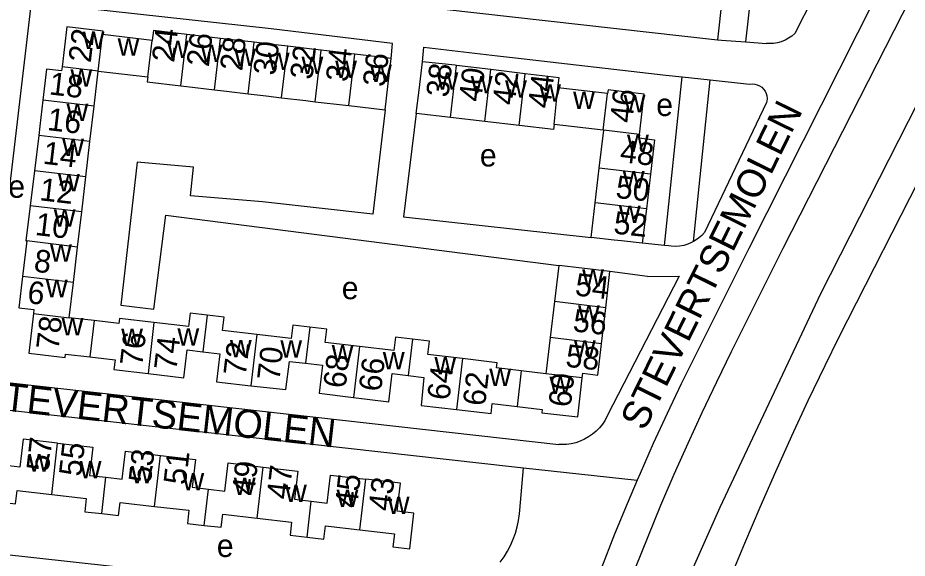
# Model space of a CAD drawing. Extents: x 159902 to 161769, y 383692 to 384875.
# Drawn here: x 161393 to 161550.6, y 384324.5 to 384420.2 of the extents above; entities that cross this region are included whole.
import ezdxf

# ---------------------------------------------------------------- set-up
doc = ezdxf.new("R2010")
doc.units = 0
for name, color, linetype in [('BLT_Basislijn', 7, 'Continuous'), ('BLT_Bebouwing', 7, 'Continuous'), ('BLT_Centroide', 7, 'Continuous'), ('BLT_Huisnummer', 7, 'Continuous'), ('BLT_Huisnummer_ tussenligend', 7, 'Continuous'), ('BLT_Onderverdeling_panden', 7, 'Continuous'), ('BLT_Straatnaam', 7, 'Continuous')]:
    doc.layers.add(name, color=color, linetype=linetype)

msp = doc.modelspace()

# ---------------------------------------------------------------- linework, layer by layer
at = {"layer": 'BLT_Basislijn'}
for p, q in [((161566.13, 384465.78), (161522.6, 384379.3)), ((161572.32, 384465.07), (161528.61, 384379.3)), ((161582.61, 384464.51), (161535.3, 384371.31)), ((161538.52, 384363.54), (161589.05, 384462.81)), ((161520.47, 384447.58), (161517, 384416.3)), ((161525.45, 384447.03), (161521.99, 384415.92)), ((161544.71, 384444.9), (161530.71, 384417.4)), ((161517, 384416.3), (161517.76, 384416.22)), ((161517.76, 384416.22), (161521.99, 384415.92)), ((161521.99, 384415.92), (161525.72, 384415.65)), ((161507.66, 384379.85), (161510.74, 384409.69)), ((161507.85, 384410), (161510.74, 384409.69)), ((161510.74, 384409.69), (161515.71, 384409.16)), ((161512.75, 384380.53), (161515.71, 384409.16)), ((161515.71, 384409.16), (161522.72, 384408.4)), ((161525.72, 384405.15), (161514.73, 384382.16)), ((161507.66, 384379.85), (161503.7, 384380.25)), ((161508.41, 384379.77), (161507.66, 384379.85)), ((161522.6, 384379.3), (161515.81, 384365.72)), ((161528.61, 384379.3), (161519.47, 384361.02)), ((161504.59, 384374.34), (161497.94, 384375.22)), ((161535.3, 384371.31), (161517.42, 384333.41)), ((161481.08, 384340.63), (161482.62, 384340.46)), ((161481.98, 384332.97), (161482.62, 384340.46)), ((161482.62, 384340.46), (161502.77, 384338.26)), ((161463.15, 384317.18), (161383.46, 384325.86))]:
    msp.add_line(p, q, dxfattribs=at)
for points in [[(161509.61, 384484.47), (161452.16, 384490.71), (161444.37, 384424.47), (161517, 384416.3)], [(161459.19, 384412.99), (161459.41, 384415.65), (161437.91, 384418.21), (161395.42, 384422.86), (161387.74, 384357.97), (161387.49, 384355.98), (161488.9, 384344.6)], [(161530.71, 384417.4), (161530.19, 384416.94), (161529.61, 384416.54), (161528.99, 384416.2), (161528.33, 384415.94), (161527.65, 384415.76), (161526.96, 384415.65), (161526.26, 384415.62), (161525.72, 384415.65)], [(161464.72, 384412.35), (161464.96, 384414.95), (161478.04, 384413.44), (161481.21, 384413.08), (161507.85, 384410)], [(161522.72, 384408.4), (161523.17, 384408.45), (161523.63, 384408.42), (161524.07, 384408.31), (161524.48, 384408.12), (161524.86, 384407.87), (161525.19, 384407.55), (161525.45, 384407.18), (161525.65, 384406.77), (161525.77, 384406.33), (161525.82, 384405.88), (161525.78, 384405.43), (161525.72, 384405.15)], [(161458.12, 384403.87), (161455.96, 384385.38), (161436.42, 384387.6), (161423.61, 384388.66), (161424.15, 384393.7), (161414.18, 384394.6), (161411.29, 384369.3), (161417.16, 384368.59), (161419.26, 384385.22), (161488.88, 384376.28)], [(161463.65, 384403.23), (161461.39, 384384.91), (161494.65, 384381.24)], [(161514.73, 384382.16), (161514.23, 384381.61), (161513.67, 384381.13), (161513.07, 384380.71), (161512.75, 384380.53)], [(161512.75, 384380.53), (161512.43, 384380.35), (161511.74, 384380.07), (161511.04, 384379.86), (161510.31, 384379.73), (161509.58, 384379.68), (161508.84, 384379.72), (161508.41, 384379.77)], [(161504.59, 384374.34), (161510.23, 384374.41), (161497.49, 384349.66)], [(161515.81, 384365.72), (161513.16, 384360.54), (161510.59, 384355.32), (161508.08, 384350.07), (161505.65, 384344.78), (161503.29, 384339.46), (161502.77, 384338.26)], [(161505.05, 384281.8), (161507.22, 384288.35), (161509.47, 384294.89), (161511.8, 384301.39), (161514.2, 384307.87), (161516.68, 384314.32), (161519.23, 384320.74), (161521.86, 384327.13), (161524.56, 384333.49), (161527.33, 384339.82), (161530.18, 384346.11), (161533.1, 384352.38), (161536.09, 384358.6), (161538.52, 384363.54)], [(161519.47, 384361.02), (161516.82, 384355.64), (161514.24, 384350.22), (161511.74, 384344.78), (161509.31, 384339.29), (161506.95, 384333.78), (161504.66, 384328.24), (161502.45, 384322.66), (161500.32, 384317.06), (161498.26, 384311.43), (161496.27, 384305.77), (161494.36, 384300.09), (161492.53, 384294.38), (161490.77, 384288.65), (161490.23, 384286.84)], [(161383.46, 384325.86), (161386.25, 384351.26), (161481.08, 384340.63)], [(161497.49, 384349.66), (161497.09, 384348.92), (161496.63, 384348.22), (161496.11, 384347.56), (161495.52, 384346.96), (161494.88, 384346.41), (161494.19, 384345.93), (161493.46, 384345.52), (161492.69, 384345.18), (161491.9, 384344.91), (161491.08, 384344.72), (161490.25, 384344.61), (161489.41, 384344.58), (161488.9, 384344.6)], [(161502.77, 384338.26), (161501, 384334.11), (161498.78, 384328.73), (161496.32, 384322.46)], [(161517.42, 384333.41), (161505.94, 384307.49)], [(161478.53, 384323.76), (161479.21, 384324.71), (161479.82, 384325.7), (161480.35, 384326.73), (161480.82, 384327.8), (161481.21, 384328.9), (161481.53, 384330.02), (161481.77, 384331.16), (161481.93, 384332.32), (161481.98, 384332.97)]]:
    msp.add_lwpolyline(points, dxfattribs=at)
at = {"layer": 'BLT_Bebouwing'}
for p, q in [((161416.82, 384416.18), (161408.04, 384417.19)), ((161424.06, 384417.11), (161422.99, 384417.23)), ((161428.95, 384416.53), (161424.06, 384417.11)), ((161431.08, 384416.28), (161428.95, 384416.53)), ((161434.9, 384415.84), (161431.08, 384416.28)), ((161438.11, 384415.46), (161434.9, 384415.84)), ((161440.86, 384415.14), (161438.11, 384415.46)), ((161445.14, 384414.63), (161440.86, 384415.14)), ((161446.82, 384414.44), (161445.14, 384414.63)), ((161452.16, 384413.81), (161446.82, 384414.44)), ((161452.78, 384413.74), (161452.16, 384413.81)), ((161459.19, 384412.99), (161452.78, 384413.74)), ((161406.55, 384404.51), (161407.29, 384410.75)), ((161407.29, 384410.75), (161416.07, 384409.72)), ((161476.87, 384411.01), (161470.8, 384411.75)), ((161482.94, 384410.26), (161476.87, 384411.01)), ((161421.92, 384408.12), (161422.99, 384407.99)), ((161422.99, 384407.99), (161427.88, 384407.42)), ((161427.88, 384407.42), (161430.01, 384407.17)), ((161430.01, 384407.17), (161433.84, 384406.72)), ((161497.51, 384406.79), (161488.75, 384407.79)), ((161433.84, 384406.72), (161437.04, 384406.34)), ((161437.04, 384406.34), (161439.79, 384406.02)), ((161439.79, 384406.02), (161444.07, 384405.52)), ((161405.82, 384398.27), (161406.55, 384404.51)), ((161444.07, 384405.52), (161445.75, 384405.32)), ((161445.75, 384405.32), (161451.09, 384404.69)), ((161451.09, 384404.69), (161451.71, 384404.62)), ((161451.71, 384404.62), (161458.12, 384403.87)), ((161469.73, 384402.52), (161463.65, 384403.23)), ((161475.8, 384401.82), (161469.73, 384402.52)), ((161481.88, 384401.11), (161475.8, 384401.82)), ((161496.76, 384400.28), (161488.06, 384401.3)), ((161396.76, 384399.33), (161395.99, 384393.09)), ((161496.08, 384393.52), (161496.87, 384400.27)), ((161496.87, 384400.27), (161496.76, 384400.28)), ((161405.09, 384392.02), (161405.82, 384398.27)), ((161395.99, 384393.09), (161395.23, 384386.85)), ((161495.37, 384387.41), (161496.08, 384393.52)), ((161404.36, 384385.78), (161405.09, 384392.02)), ((161505.13, 384392.46), (161504.42, 384386.35)), ((161494.65, 384381.24), (161495.37, 384387.41)), ((161403.62, 384379.54), (161404.36, 384385.78)), ((161504.42, 384386.35), (161503.7, 384380.25)), ((161394.62, 384380.67), (161393.86, 384374.35)), ((161402.89, 384373.29), (161403.62, 384379.54)), ((161488.88, 384376.28), (161488.13, 384369.9)), ((161497.21, 384368.83), (161497.94, 384375.22)), ((161402.16, 384367.05), (161402.89, 384373.29)), ((161488.13, 384369.9), (161487.38, 384363.52)), ((161496.47, 384362.45), (161497.21, 384368.83)), ((161406.55, 384366.54), (161402.16, 384367.05)), ((161487.38, 384363.52), (161486.63, 384357.14)), ((161486.63, 384357.14), (161482.24, 384357.65))]:
    msp.add_line(p, q, dxfattribs=at)
for points in [[(161408.04, 384417.19), (161408.14, 384417.79), (161401.71, 384418.55), (161400.89, 384411.5)], [(161422.99, 384417.23), (161417.06, 384417.93), (161416.82, 384416.18)], [(161458.12, 384403.87), (161458.61, 384408.02), (161459.19, 384412.99)], [(161463.65, 384403.23), (161464.14, 384407.38), (161464.72, 384412.35)], [(161470.8, 384411.75), (161470.54, 384411.78), (161464.72, 384412.35)], [(161400.89, 384411.5), (161400.8, 384410.78), (161398.11, 384411.1), (161397.48, 384405.57)], [(161416.07, 384409.72), (161415.96, 384408.82), (161421.92, 384408.12)], [(161488.75, 384407.79), (161488.97, 384409.53), (161482.94, 384410.26)], [(161503.22, 384399.53), (161504.02, 384406.63), (161500, 384407.11), (161497.62, 384407.39), (161497.51, 384406.79)], [(161397.48, 384405.57), (161396.96, 384400.99), (161396.76, 384399.33)], [(161488.06, 384401.3), (161487.95, 384400.4), (161481.88, 384401.11)], [(161503.22, 384399.53), (161503.15, 384398.9), (161505.84, 384398.56), (161505.13, 384392.46)], [(161395.23, 384386.85), (161394.48, 384380.67), (161394.62, 384380.67)], [(161503.7, 384380.25), (161500, 384380.66), (161498.73, 384380.8), (161494.65, 384381.24)], [(161497.94, 384375.22), (161492.98, 384375.8), (161488.88, 384376.28)], [(161393.86, 384374.35), (161393.2, 384368.83), (161395.89, 384368.51), (161395.8, 384367.78)], [(161395.8, 384367.78), (161394.99, 384360.76), (161401.42, 384360), (161401.48, 384360.59), (161405.79, 384360.11)], [(161426.59, 384367.48), (161423.58, 384367.83), (161423.3, 384365.5), (161417.17, 384366.22)], [(161417.17, 384366.22), (161411.05, 384366.93), (161410.94, 384366.02), (161406.55, 384366.54)], [(161435.41, 384364.09), (161429.32, 384364.8), (161429.6, 384367.12), (161426.59, 384367.48)], [(161444.78, 384365.35), (161441.77, 384365.71), (161441.5, 384363.37), (161435.41, 384364.09)], [(161453.59, 384361.95), (161447.52, 384362.66), (161447.79, 384365), (161444.78, 384365.35)], [(161462.95, 384363.26), (161459.95, 384363.62), (161459.67, 384361.23), (161453.59, 384361.95)], [(161471.82, 384359.8), (161465.68, 384360.52), (161465.96, 384362.91), (161462.95, 384363.26)], [(161493.05, 384356.39), (161493.14, 384357.21), (161495.83, 384356.9), (161496.47, 384362.45)], [(161405.79, 384360.11), (161410.28, 384359.61), (161410.08, 384357.9), (161416.11, 384357.17)], [(161416.11, 384357.17), (161422.43, 384356.41), (161423.05, 384361.38), (161425.83, 384361.03)], [(161425.83, 384361.03), (161428.86, 384360.66), (161428.24, 384355.68), (161434.35, 384355.01)], [(161434.35, 384355.01), (161440.56, 384354.32), (161441.19, 384359.32), (161444.04, 384358.99)], [(161444.04, 384358.99), (161447.01, 384358.64), (161446.42, 384353.67), (161452.53, 384352.92)], [(161482.24, 384357.65), (161477.85, 384358.17), (161477.96, 384359.08), (161471.82, 384359.8)], [(161452.53, 384352.92), (161458.79, 384352.15), (161459.37, 384357.18), (161462.2, 384356.82)], [(161462.2, 384356.82), (161464.97, 384356.46), (161464.5, 384351.5), (161470.77, 384350.79)], [(161481.5, 384351.33), (161485.93, 384350.81), (161485.87, 384350.21), (161492.25, 384349.47), (161493.05, 384356.39)], [(161470.77, 384350.79), (161476.92, 384350.09), (161477.12, 384351.85), (161481.5, 384351.33)], [(161400.1, 384344.84), (161393.99, 384345.52), (161393.42, 384340.56), (161390.38, 384340.91), (161389.64, 384334.44), (161392.65, 384334.1), (161392.95, 384336.43), (161399.06, 384335.73)], [(161400.1, 384344.84), (161406.33, 384344.13), (161405.75, 384339.13), (161408.64, 384338.81)], [(161408.64, 384338.81), (161411.55, 384338.48), (161412.11, 384343.4), (161418.3, 384342.67)], [(161418.3, 384342.67), (161424.5, 384341.95), (161423.93, 384337.05), (161426.83, 384336.69)], [(161426.83, 384336.69), (161429.73, 384336.33), (161430.33, 384341.32), (161436.49, 384340.6)], [(161436.49, 384340.6), (161442.63, 384339.88), (161442.06, 384334.91), (161445.02, 384334.55)], [(161445.02, 384334.55), (161447.85, 384334.21), (161448.46, 384339.19), (161454.69, 384338.46)], [(161453.66, 384329.48), (161459.76, 384328.78), (161459.49, 384326.45), (161462.49, 384326.1), (161463.22, 384332.44), (161460.27, 384332.79), (161460.83, 384337.74), (161454.69, 384338.46)], [(161399.06, 384335.73), (161405.16, 384335.03), (161404.9, 384332.69), (161407.9, 384332.35)], [(161407.9, 384332.35), (161410.9, 384332.01), (161411.17, 384334.34), (161417.27, 384333.64)], [(161417.27, 384333.64), (161423.37, 384332.95), (161423.1, 384330.61), (161426.09, 384330.27)], [(161426.09, 384330.27), (161429.08, 384329.93), (161429.35, 384332.26), (161435.45, 384331.56)], [(161435.45, 384331.56), (161441.56, 384330.86), (161441.29, 384328.53), (161444.29, 384328.19)], [(161444.29, 384328.19), (161447.29, 384327.84), (161447.56, 384330.18), (161453.66, 384329.48)]]:
    msp.add_lwpolyline(points, dxfattribs=at)
at = {"layer": 'BLT_Onderverdeling_panden'}
for p, q in [((161407.29, 384410.75), (161408.04, 384417.19)), ((161421.92, 384408.12), (161422.99, 384417.23)), ((161416.07, 384409.72), (161416.82, 384416.18)), ((161427.88, 384407.42), (161428.95, 384416.53)), ((161433.84, 384406.72), (161434.9, 384415.84)), ((161439.79, 384406.02), (161440.86, 384415.14)), ((161445.75, 384405.32), (161446.82, 384414.44)), ((161451.71, 384404.62), (161452.78, 384413.74)), ((161407.29, 384410.75), (161400.89, 384411.5)), ((161469.73, 384402.52), (161470.8, 384411.75)), ((161475.8, 384401.82), (161476.87, 384411.01)), ((161481.88, 384401.11), (161482.94, 384410.26)), ((161488.06, 384401.3), (161488.75, 384407.79)), ((161406.55, 384404.51), (161397.48, 384405.57)), ((161496.76, 384400.28), (161497.51, 384406.79)), ((161405.82, 384398.27), (161396.76, 384399.33)), ((161503.22, 384399.53), (161496.87, 384400.27)), ((161405.09, 384392.02), (161395.99, 384393.09)), ((161505.13, 384392.46), (161496.08, 384393.52)), ((161404.36, 384385.78), (161395.23, 384386.85)), ((161504.42, 384386.35), (161495.37, 384387.41)), ((161403.62, 384379.54), (161394.62, 384380.67)), ((161402.89, 384373.29), (161393.86, 384374.35)), ((161497.21, 384368.83), (161488.13, 384369.9)), ((161395.8, 384367.78), (161402.16, 384367.05)), ((161406.55, 384366.54), (161405.79, 384360.11)), ((161417.17, 384366.22), (161416.11, 384357.17)), ((161426.59, 384367.48), (161425.83, 384361.03)), ((161444.78, 384365.35), (161444.04, 384358.99)), ((161435.41, 384364.09), (161434.35, 384355.01)), ((161462.95, 384363.26), (161462.2, 384356.82)), ((161496.47, 384362.45), (161487.38, 384363.52)), ((161453.59, 384361.95), (161452.53, 384352.92)), ((161471.82, 384359.8), (161470.77, 384350.79)), ((161482.24, 384357.65), (161481.5, 384351.33)), ((161493.05, 384356.39), (161486.63, 384357.14)), ((161399.06, 384335.73), (161400.1, 384344.84)), ((161417.27, 384333.64), (161418.3, 384342.67)), ((161435.45, 384331.56), (161436.49, 384340.6)), ((161407.9, 384332.35), (161408.64, 384338.81)), ((161453.66, 384329.48), (161454.69, 384338.46)), ((161426.09, 384330.27), (161426.83, 384336.69)), ((161444.29, 384328.19), (161445.02, 384334.55))]:
    msp.add_line(p, q, dxfattribs=at)

# ---------------------------------------------------------------- texts
at = {"layer": 'BLT_Centroide'}
for s, p in [('w', (161404.52, 384414.64)), ('w', (161410.72, 384413.47)), ('w', (161419.47, 384413.03)), ('w', (161425.44, 384412.33)), ('w', (161431.39, 384411.62)), ('w', (161437.34, 384410.94)), ('w', (161443.31, 384410.22)), ('w', (161449.27, 384409.53)), ('w', (161455.45, 384408.81)), ('w', (161402.36, 384408)), ('w', (161467.23, 384407.45)), ('w', (161473.3, 384406.77)), ('w', (161479.38, 384406.05)), ('w', (161485.42, 384405.33)), ('w', (161491.43, 384404.03)), ('w', (161500.39, 384403.45)), ('e', (161506.17, 384402.78)), ('w', (161401.66, 384401.91)), ('w', (161500.99, 384396.38)), ('w', (161400.91, 384395.69)), ('e', (161474.91, 384393.84)), ('w', (161500.24, 384389.94)), ('e', (161391.35, 384388.3)), ('w', (161400.16, 384389.44)), ('w', (161499.54, 384383.84)), ('w', (161399.41, 384383.19)), ('w', (161398.75, 384376.97)), ('w', (161493.04, 384372.56)), ('w', (161398.01, 384370.69)), ('e', (161450.44, 384370.33)), ('w', (161492.3, 384366.19)), ('w', (161400.8, 384363.91)), ('w', (161411.35, 384362.06)), ('w', (161421.32, 384362.12)), ('w', (161430.62, 384360.03)), ('w', (161439.55, 384360)), ('w', (161491.58, 384359.97)), ('w', (161448.66, 384359.12)), ('w', (161457.72, 384357.88)), ('w', (161466.86, 384357.03)), ('w', (161476.59, 384354.94)), ('w', (161487.24, 384353.56)), ('w', (161394.89, 384339.81)), ('w', (161404, 384338.59)), ('w', (161413.12, 384337.69)), ('w', (161422.2, 384336.47)), ('w', (161431.31, 384335.62)), ('w', (161440.39, 384334.41)), ('w', (161449.52, 384333.53)), ('w', (161458.59, 384332.28)), ('e', (161428.3, 384324.67))]:
    msp.add_text(s, height=4, dxfattribs=at).set_placement(p)
at = {"layer": 'BLT_Huisnummer'}
for s, rotation, p in [('22', 83.302, (161405.96, 384412.11)), ('24', 83.3076, (161420.74, 384412.15)), ('28', 83.3029, (161432.8, 384410.64)), ('32', 83.3611, (161445.22, 384409.12)), ('36', 83.355, (161458.1, 384407.83)), ('38', 83.355, (161469.33, 384405.98)), ('18', 353.3078, (161398.47, 384406.62)), ('44', 83.3507, (161487.38, 384404)), ('46', 84.0561, (161501.93, 384401.45)), ('14', 353.3053, (161397.37, 384394.34)), ('48', 353.3423, (161499.62, 384394.64)), ('10', 353.3089, (161395.99, 384381.72)), ('52', 353.8685, (161498.48, 384381.97)), ('54', 353.308, (161491.65, 384371.01)), ('6', 353.4492, (161394.6, 384369.65)), ('78', 83.3088, (161400.24, 384361.21)), ('76', 83.3104, (161415.08, 384358.36)), ('72', 83.311, (161433.42, 384356.64)), ('58', 353.3865, (161489.98, 384358.4)), ('68', 83.311, (161451.11, 384354.44)), ('64', 83.3075, (161469.52, 384352.32)), ('60', 83.3891, (161491.01, 384351.08)), ('57', 83.4672, (161398.51, 384339.71)), ('55', 83.4672, (161404.27, 384338.83)), ('51', 83.4621, (161422.81, 384337.33)), ('47', 83.4673, (161441.07, 384334.76)), ('43', 83.4208, (161459.12, 384332.67))]:
    msp.add_text(s, height=4, rotation=rotation, dxfattribs=at).set_placement(p)
at = {"layer": 'BLT_Huisnummer_ tussenligend'}
for s, rotation, p in [('26', 83.3076, (161426.88, 384411.38)), ('30', 83.3029, (161438.7, 384409.86)), ('34', 83.3611, (161451.55, 384408.7)), ('40', 83.3507, (161475.14, 384405.19)), ('42', 83.3507, (161481.09, 384404.59)), ('16', 353.3053, (161398.14, 384400.3)), ('12', 353.3089, (161396.77, 384387.87)), ('50', 353.3423, (161498.85, 384388.3)), ('8', 353.4492, (161395.76, 384375.23)), ('56', 353.308, (161491.27, 384364.66)), ('74', 83.311, (161421.13, 384357.59)), ('70', 83.311, (161439.39, 384355.78)), ('66', 83.3075, (161457.41, 384353.86)), ('62', 83.3891, (161475.84, 384351.29)), ('53', 83.4621, (161416.61, 384337.65)), ('49', 83.4673, (161434.92, 384335.53)), ('45', 83.4208, (161453.16, 384333.24))]:
    msp.add_text(s, height=4, rotation=rotation, dxfattribs=at).set_placement(p)
at = {"layer": 'BLT_Straatnaam'}
for rotation, p in [(63.725, (161504.09, 384346.82)), (353.6054, (161385.96, 384351.12))]:
    msp.add_text('STEVERTSEMOLEN', height=5, rotation=rotation, dxfattribs=at).set_placement(p)

doc.saveas('drawing.dxf')
